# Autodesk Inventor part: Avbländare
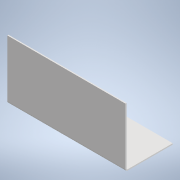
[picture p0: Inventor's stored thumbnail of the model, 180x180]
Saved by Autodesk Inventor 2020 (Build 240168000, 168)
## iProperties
Created: 2019-06
Part Number: Avbländare
Material: Generic
Document SubType Name: Sheet Metal
Designer: cl
Density: 1 g/cm^3
Sheet Metal Rule: Default
Appearance: Default
Author: cl
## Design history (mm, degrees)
node "Face1"
  sketch "Sketch2"
    geometry: L1 (0, 0)-(50, 0); L2 (50, 0)-(50, -20); L3 (50, -20)-(0, -20); L4 (0, -20)-(0, 0)
    constraints: 8 end point, 2 parallel, 1 horizontal, 1 perpendicular
    dimensions: "d0" = 50 distance of L2.end L3.end; "d1" = 20 distance of L1.end L2.end
node "Flange1"
body "Solid1"
face "Plate1" dims "d2" = 0.5 (= Thickness)
sketch "Sketch3"
  geometry: L1 through (-25, 0) direction (1, 0); L2 through (0, 12.5) direction (0, 1); L3 (0, 25)-(-50, 25); L4 (-50, 25)-(-50, 0)
  constraints: 6 end point, 1 horizontal, 1 perpendicular, 1 vertical
face "Plate2" dims "d2" = 0.5 (= Thickness), "d3" = 0.5 (= BendReliefWidth), "d4" = 0.25 (= BendReliefDepth), "d5" = 1 (= MinimumRemnant), "d6" = 0.5 (= TransitionRadius), "d7" = 25, "d8" = 90 deg, "d9" = 0.5 (= BendRadius), "d10" = 2 (= CornerReliefSize), "d11" = 0.5 (= GapSize), "d12" = 0.5 (= JacobiRadiusSize), "SeamGap" = 0.01
bend "Bend1" dims "d2" = 0.5 (= Thickness), "d3" = 0.5 (= BendReliefWidth), "d4" = 0.25 (= BendReliefDepth), "d5" = 1 (= MinimumRemnant), "d6" = 0.5 (= TransitionRadius), "d7" = 25, "d8" = 90 deg, "d9" = 0.5 (= BendRadius), "SeamGap" = 0.01
feature "Corner1" dims "d7" = 25, "d8" = 90 deg, "d10" = 2 (= CornerReliefSize), "d11" = 0.5 (= GapSize), "d12" = 0.5 (= JacobiRadiusSize)
other parameters: "Thickness" = 0.5, "KFactor" = 4.4, "BendRadius" = 0.5 (= Thickness), "BendReliefWidth" = 0.5 (= Thickness), "BendReliefDepth" = 0.25 (= 0.5 x Thickness), "CornerReliefSize" = 2 (= 4 x Thickness), "MinimumRemnant" = 1 (= 2 x Thickness), "TransitionRadius" = 0.5 (= BendRadius), "JacobiRadiusSize" = 0.5 (= Thickness), "GapSize" = 0.5 (= Thickness)
